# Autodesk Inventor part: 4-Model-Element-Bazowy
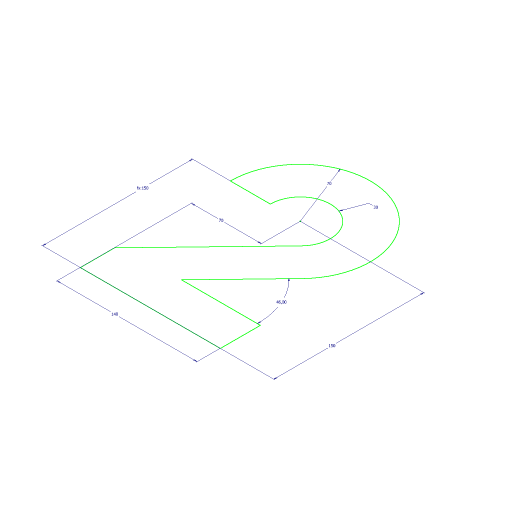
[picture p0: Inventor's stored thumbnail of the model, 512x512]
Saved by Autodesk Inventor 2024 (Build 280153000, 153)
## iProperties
Company: ATC
Shininess: 21.0
Length Units: 11269
Angle Units: 11279
Time Units: 11290
Mass Units: 11283
Length Display Precision: 3
Angle Display Precision: 2
Compacted: True
Created: 2023-03
Part Number: 4-Model-Element-Bazowy
Document SubType Name: Modeling
Designer: Andrzej Jaskulski
Material: Kurs-AJ
Density: 1 g/cm^3
Appearance: Kurs-AJ
Checked By: A.J.
Engr Approved By: Andrzej Jaskulski
Mfg Approved By: Andrzej Jaskulski
Authority: A.J.
Density: 0.0
Volumn: 0.0
Area: 0.0
PropertySet Name: Model Information
Control State: 0
Master: False
Checked Out: False
Title: A.J.: Kurs R2024-MEP
Author: Andrzej Jaskulski
Revision Number: 1/24
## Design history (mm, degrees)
sketch "Zarys dwójki"
  geometry: L1 (140, 0.063)-(0, 0.063) reference; L2 (0, 0.063)-(0, 34.389) reference; L3 (0, 150.063)-(40, 150.063); L4 (140, 0.063)-(140, 40.063); L5 (140, 40.063)-(61.086, 40.063); L6 (61.086, 40.063)-(120.354, 101.437); L7 (91.58, 129.223)-(0, 34.389); A1 r 30 centre (70, 150.063) between (91.58, 129.223) and (40, 150.063); A2 r 70 centre (70, 150.063) between (120.354, 101.437) and (0, 150.063)
  constraints: 14 end point, 4 perpendicular, 4 point on circle, 2 centre point, 2 parallel, 2 tangent, 1 coincident
  dimensions: "d0" = 140 distance of L1.start L1.end; "d1" = 150 vertical distance of A1.centre L1.end; "d2" = 70 horizontal distance of L1.end A1.centre; "d3" = 46 deg angle of L6 L5; "d4" = 150 distance of L3.start L1.end (= d1); "d5" = 30 radius of A1; "d6" = 70 radius of A2
node "Korpusy bryłowe"
node "Korpusy powierzchniowe"
other parameters: "d9" = 90 deg
